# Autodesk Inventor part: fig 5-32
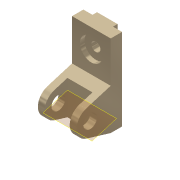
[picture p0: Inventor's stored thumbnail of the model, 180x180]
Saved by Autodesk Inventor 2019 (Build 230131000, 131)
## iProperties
Shininess: 65.0
Angle Display Precision: 2
Document Length Units: 11269
Document Angle Units: 11279
Document Time Units: 11290
Document Mass Units: 11283
Document Length Units Precision: 3
Document Angle Units Precision: 2
Created: 2001-11
Part Number: fig 5-32
Document SubType Name: Modeling
Designer: Renu Muthoo
Density: 1 g/cm^3
Material: Generic
Appearance: Metal-Titanium (Polished)
Density: 0.0
Volumn: 0.0
Area: 0.0
PropertySet Name: Model Information
Control State: 0
Master: False
Checked Out: False
Author: Renu Muthoo
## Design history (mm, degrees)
node "Sketch1"
sketch "Sketch2"
  geometry: L1 (33.257, 104.664)-(33.257, -75.336); L2 (33.257, -75.336)-(8.257, -75.336); L3 (8.257, -75.336)-(-45.451, -59.045); L4 (-45.451, -1.628)-(8.257, 14.664); L5 (8.257, 14.664)-(8.257, 104.664); L6 (8.257, 104.664)-(33.257, 104.664); C1 r 15 at (-36.743, -30.336); A1 r 30 centre (-36.743, -30.336) between (-45.451, -1.628) and (-45.451, -59.045)
  constraints: 12 end point, 2 centre point, 2 equal length, 2 parallel, 2 point on circle, 2 tangent, 1 coincident, 1 perpendicular, 1 vertical
  dimensions: "d0" = 180 distance of L1.start L1.end; "d1" = 30 radius of A1; "d2" = 25 distance of L5.end L1.start; "d3" = 45 distance from line of L2 A1.centre; "d4" = 70 distance from line of L1 A1.centre; "d5" = 30 diameter of C1
extrude "Extrusion1" new body sketch "Sketch2" distance "d6" = 85; taper "d7" = 0 deg
workplane "Work Plane1"
sketch "Sketch3"
  geometry: L1 (15, 62.364)-(70, 62.364); L2 (70, 62.364)-(70, -52.386); L3 (70, -52.386)-(15, -52.386); L4 (15, -52.386)-(15, 62.364); L5 (0, -45)-(0, -28.708) reference
  constraints: 8 end point, 2 parallel, 1 horizontal, 1 perpendicular
  dimensions: "d8" = 55 distance of L1.start L1.end; "d9" = 15 distance between parallel lines of L5 L4
extrude "Extrusion2" cut sketch "Sketch3" distance "d10" = 50; taper "d11" = 0 deg
sketch "Sketch4"
  geometry: L1 (0, 25)-(85, 25) reference; L2 (0, 0)-(0, 25) reference; L3 (20, 25)-(65, 25); L4 (65, 25)-(65, 35); L5 (65, 35)-(20, 35); L6 (20, 35)-(20, 25)
  constraints: 8 end point, 2 parallel, 1 horizontal, 1 perpendicular, 1 point on line
  dimensions: "d12" = 45 distance of L4.end L5.end; "d13" = 10 distance of L3.end L4.end; "d14" = 20 distance between parallel lines of L2 L6
extrude "Extrusion3" join sketch "Sketch4" stored distance "d15" = 50; taper "d16" = 0 deg
sketch "Sketch5"
  geometry: L1 (85, 0)-(85, 90) reference; L2 (0, 90)-(85, 90) reference; 1 further point
  dimensions: "d17" = 42 distance from line of L2 point (42.5, 48); "d18" = 42.5 distance from line of L1 point (42.5, 48)
hole "Hole1" sketch "Sketch5" at (42.5, 48) diameter "d19" = 20; stored, may be unused: countersink angle "d23" = 82 deg, drill point angle "d25" = 118 deg; dims "d20" = 6, "d21" = 50, "d22" = 10, "d24" = 8
workplane "Work Plane6"
body "Solid1"
